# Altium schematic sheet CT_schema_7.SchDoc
size 405 x 220 mm
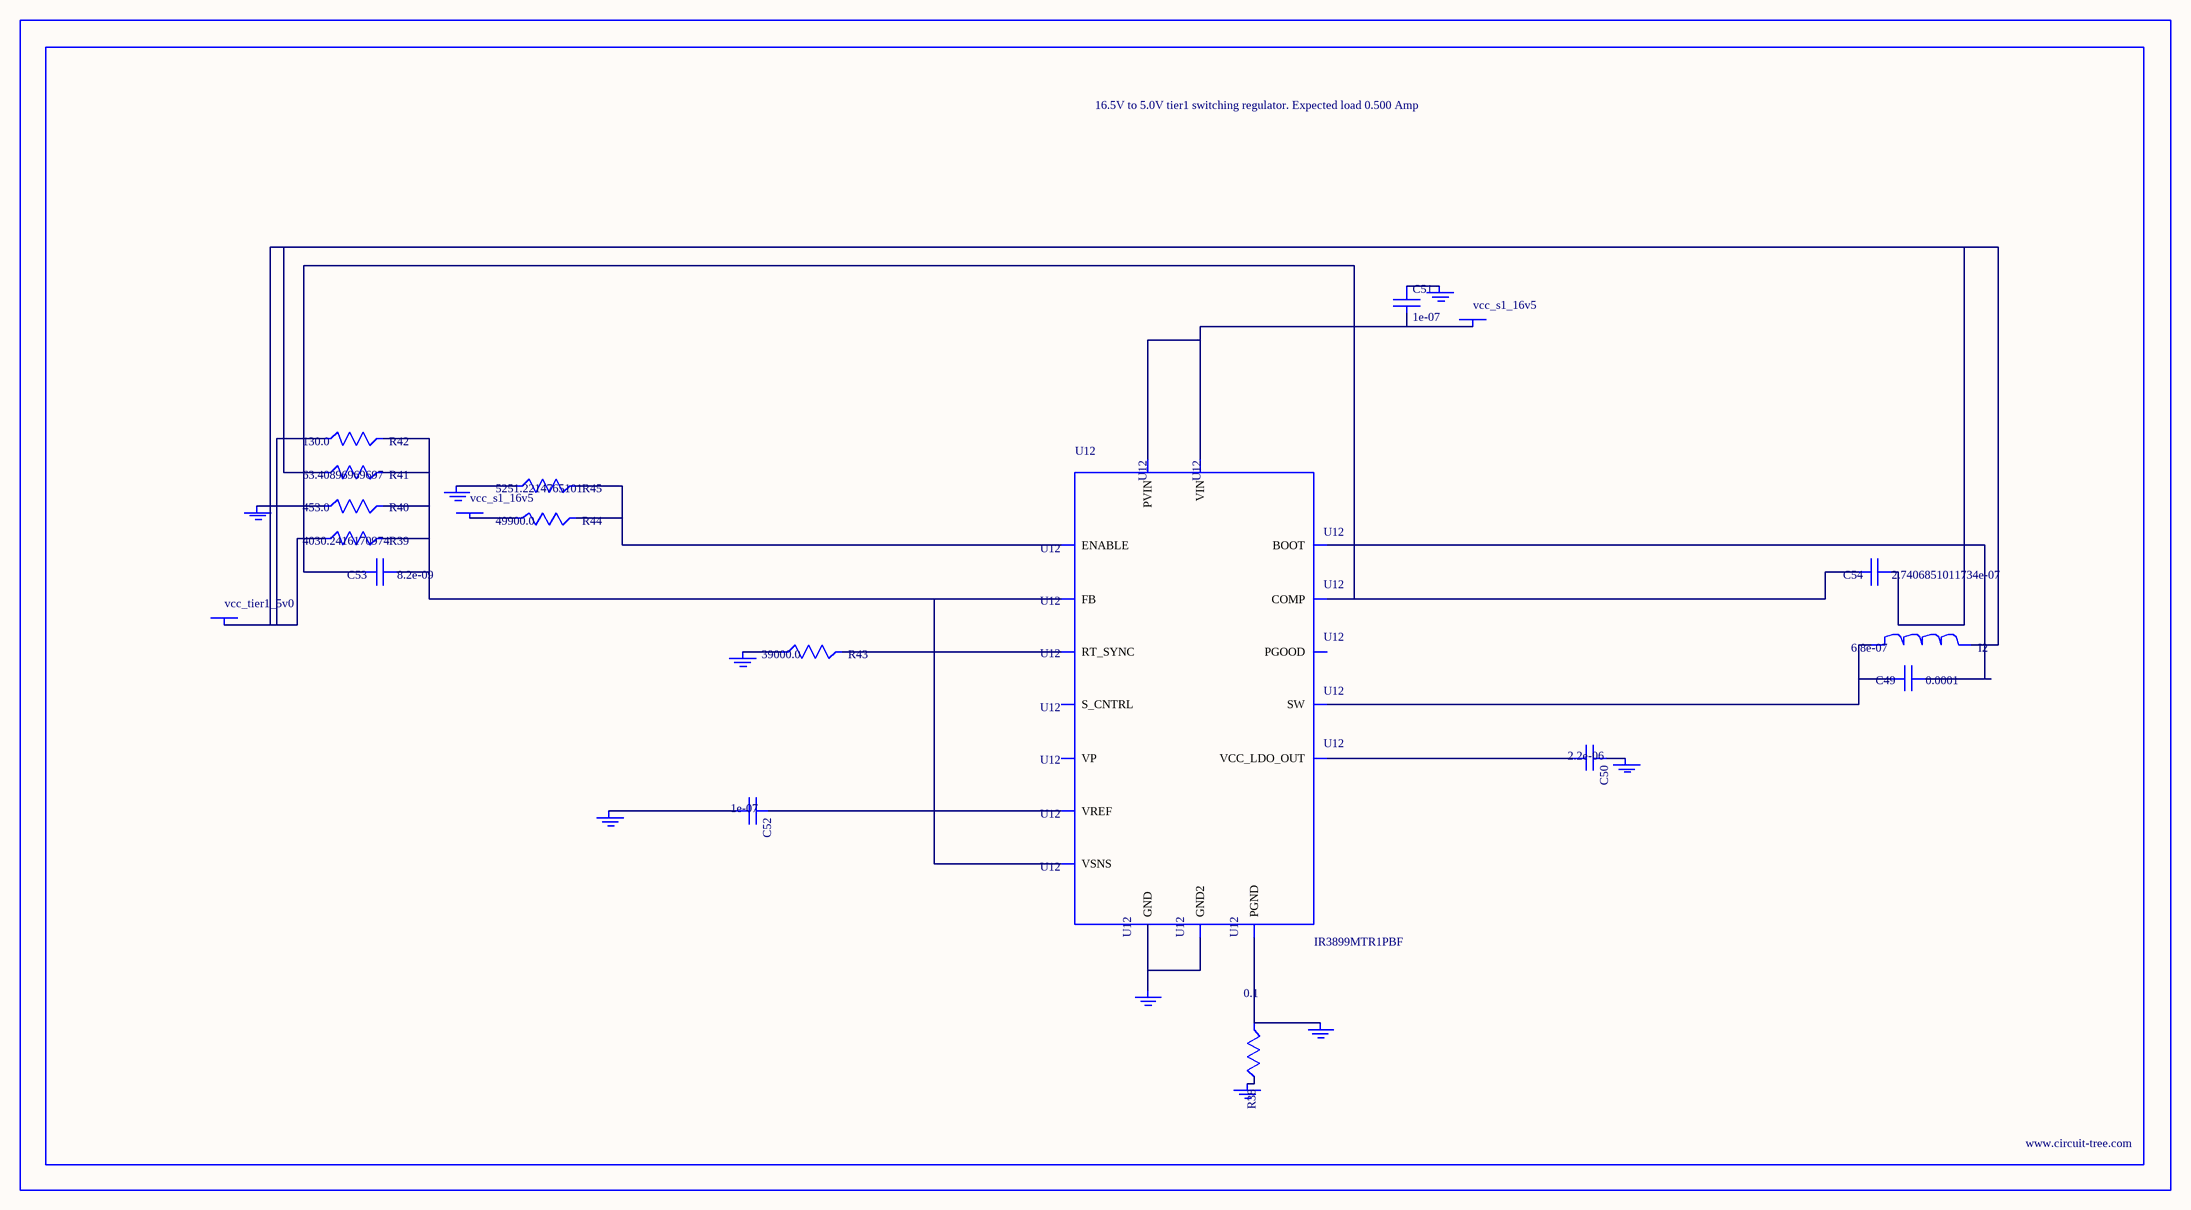
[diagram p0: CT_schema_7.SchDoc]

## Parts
BORDER6  (no value)
C49  0.0001  [C1210]
C50  2.2e-06  [C0603]
C51  1e-07  [C0402]
C52  1e-07  [C0402]
C53  8.2e-09  [C0402]
C54  2.7406851011734e-07  [R0603]
GND_INSTANCE_6_0  (no value)
GND_INSTANCE_6_1  (no value)
GND_INSTANCE_6_2  (no value)
GND_INSTANCE_6_3  (no value)
GND_INSTANCE_6_4  (no value)
GND_INSTANCE_6_5  (no value)
GND_INSTANCE_6_6  (no value)
GND_INSTANCE_6_7  (no value)
GND_INSTANCE_6_8  (no value)
I2  6.8e-07  [IND25X25CZ]
POWER_INSTANCE_6_0  vcc_s1_16v5
POWER_INSTANCE_6_1  vcc_s1_16v5
POWER_INSTANCE_6_2  vcc_tier1_5v0
R38  0.1  [R0603]
R39  4030.2416170974  [R0603]
R40  453.0  [R0603]
R41  63.40896969697  [R0603]
R42  130.0  [R0603]
R43  39000.0  [R0603]
R44  49900.0  [R0603]
R45  5251.2214765101  [R0603]
U12  IR3899MTR1PBF  [IR3899MTR1PBF]

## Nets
NetC49_1: C49.1 U12.14(BOOT)
NetC49_2: C49.2 I2.1 U12.12(SW)
NetC50_1: C50.1 GND_INSTANCE_6_4.0(GND)
NetC50_2: C50.2 U12.10(VCC_LDO_OUT)
NetC51_1: C51.1 GND_INSTANCE_6_3.0(GND)
NetC51_2: C51.2 POWER_INSTANCE_6_0.0(PWR) U12.9(VIN) U12.13(PVIN)
NetC52_1: C52.1 U12.2(VREF)
NetC52_2: C52.2 GND_INSTANCE_6_1.0(GND)
NetC53_1: C53.1 R39.2 R40.2 R41.2 R42.2 U12.1(FB) U12.8(VSNS)
NetC53_2: C53.2 C54.2 U12.3(COMP)
NetC54_1: C54.1 I2.2 POWER_INSTANCE_6_2.0(PWR) R39.1 R41.1 R42.1
NetGND_INSTANCE_6_0_0: GND_INSTANCE_6_0.0(GND) R40.1
NetGND_INSTANCE_6_2_0: GND_INSTANCE_6_2.0(GND) R43.1
NetGND_INSTANCE_6_5_0: GND_INSTANCE_6_5.0(GND) R38.2
NetGND_INSTANCE_6_6_0: GND_INSTANCE_6_6.0(GND) R38.1 U12.11(PGND)
NetGND_INSTANCE_6_7_0: GND_INSTANCE_6_7.0(GND) R45.1
NetGND_INSTANCE_6_8_0: GND_INSTANCE_6_8.0(GND) U12.4(GND) U12.17(GND2)
NetPOWER_INSTANCE_6_1_0: POWER_INSTANCE_6_1.0(PWR) R44.1
NetR43_2: R43.2 U12.5(RT_SYNC)
NetR44_2: R44.2 R45.2 U12.15(ENABLE)

Not connected (* = marked no-connect by the designer): U12 6(S_CNTRL) 7(PGOOD) 16(VP)

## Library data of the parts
BORDER6 = BORDER_PAGE6
C49 = GRM32ER61A107ME20L
C50 = C0603C225K8RACTU
C51 C52 = C0402C104K3RACTU
C53 = C0402C822K3RAC
C54 = C54
GND_INSTANCE_6_0-GND_INSTANCE_6_8 = GND
I2 = IHLP2525CZERR68M01
POWER_INSTANCE_6_0-POWER_INSTANCE_6_2 = PWR
R38 = ERJ-3RSFR10V
R39 = R39
R40 = ERJ-3EKF4530V
R41 = R41
R42 = RC0603JR-07130RL
R43 = RC0603JR-0739KL
R44 = RC0603FR-0749K9
R45 = R45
